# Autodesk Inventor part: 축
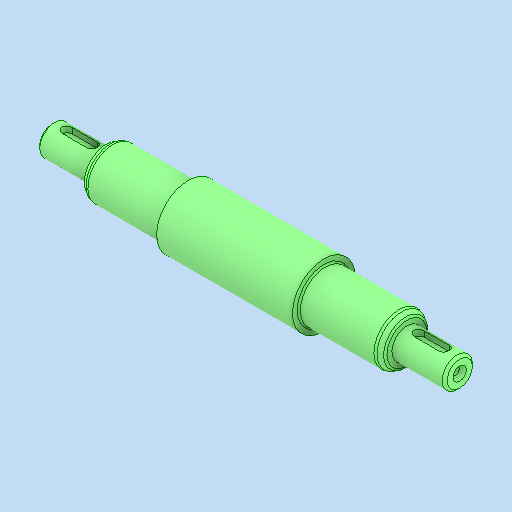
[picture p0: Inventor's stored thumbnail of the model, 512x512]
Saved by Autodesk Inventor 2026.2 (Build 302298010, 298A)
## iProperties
Created: 2026-03
Part Number: 축
Material: 강철, 탄소
Document SubType Name: Modeling
Designer: PC-2-03
Density: 7.85 g/cm^3
Appearance: 기본값
Author: jhkim
Sending System: Autodesk Inventor 2026
Preprocessor: ST-DEVELOPER v20.1
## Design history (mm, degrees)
feature "솔리드1"
node "솔리드2"
